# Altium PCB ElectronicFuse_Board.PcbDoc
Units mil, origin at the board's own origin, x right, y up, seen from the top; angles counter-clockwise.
Board outline 3505.03 x 1865.03 mil, 2 copper layers (Top Layer, Bottom Layer), stack 58.4 mil thick; 30 components, 15 nets, 72 pads, 10 vias.
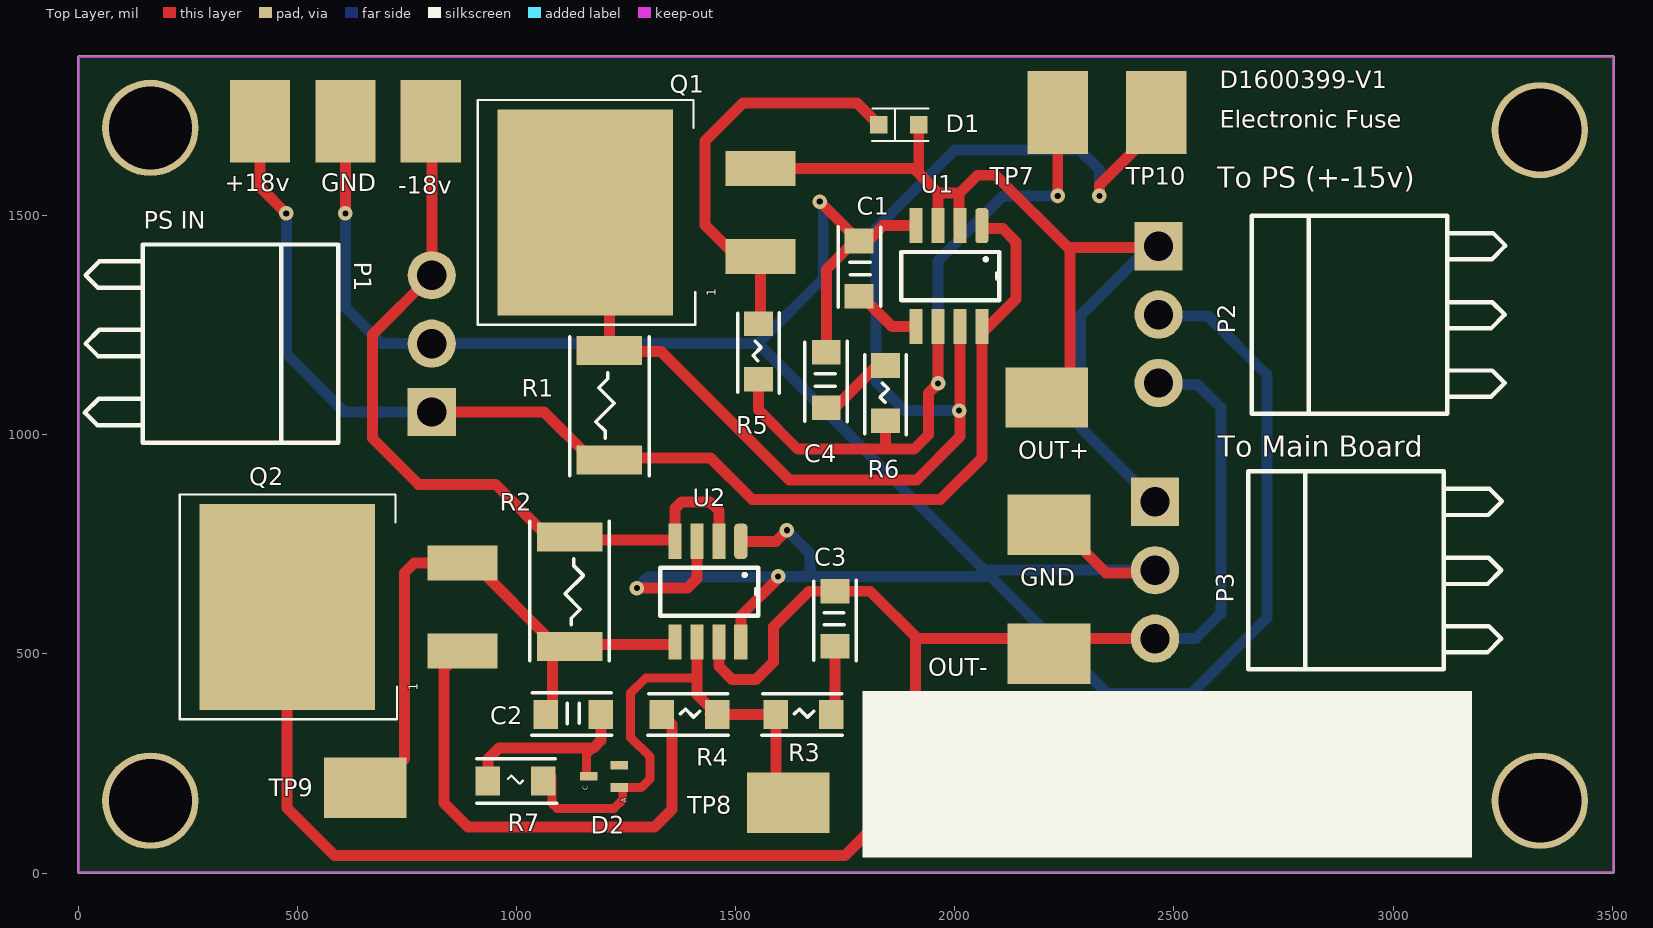
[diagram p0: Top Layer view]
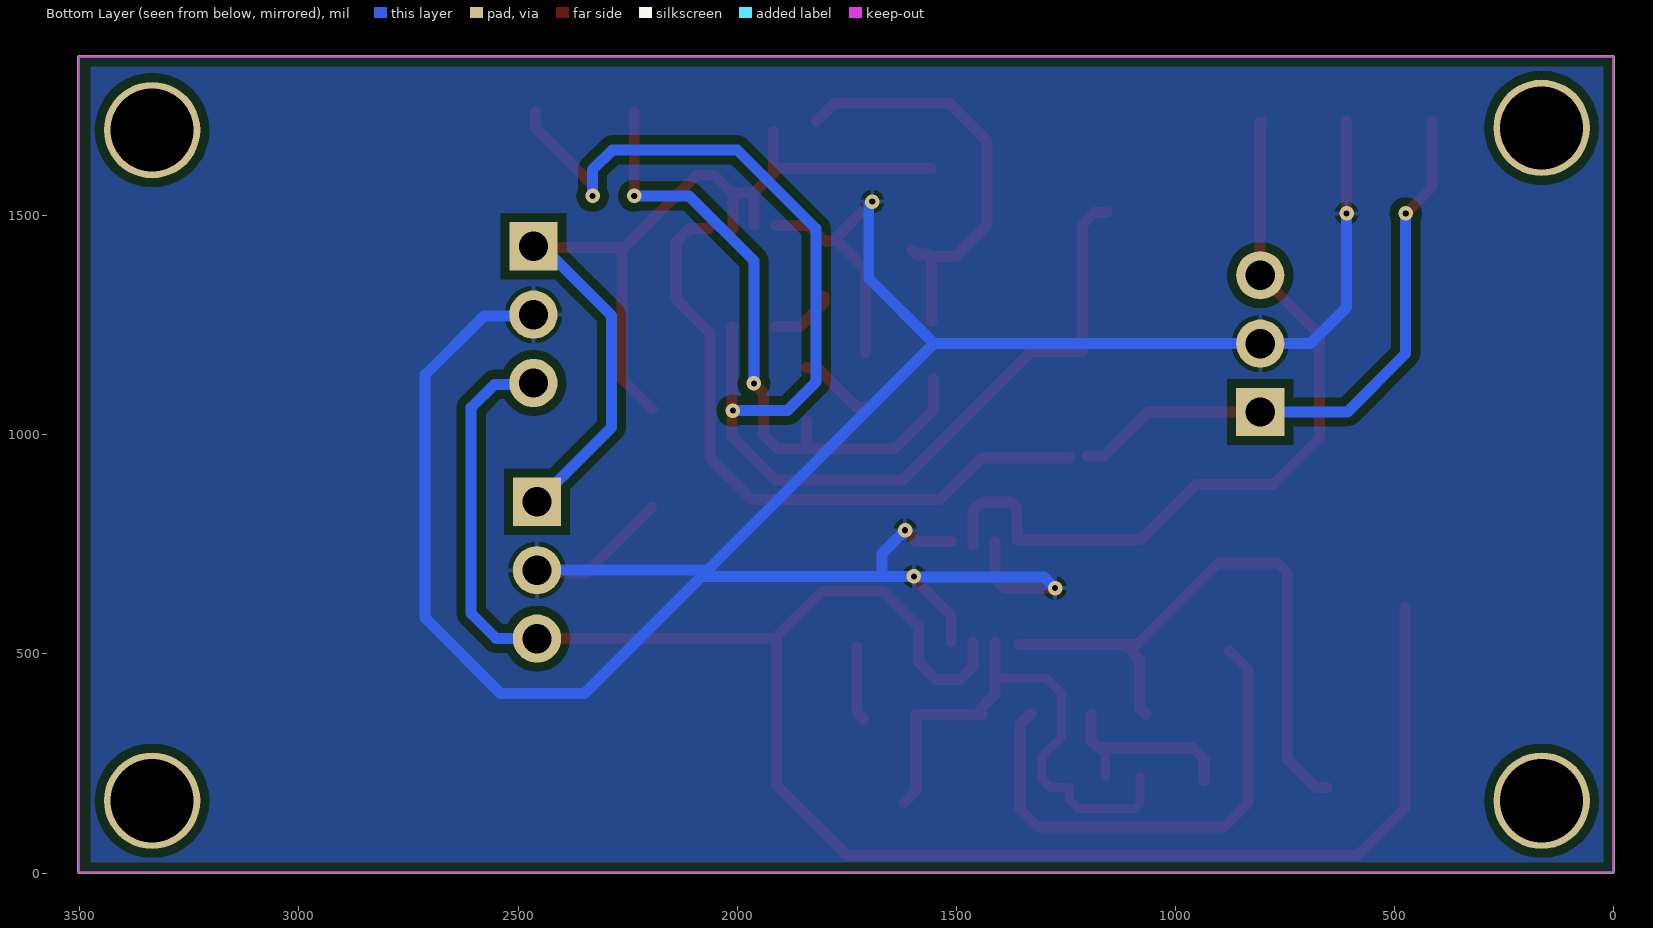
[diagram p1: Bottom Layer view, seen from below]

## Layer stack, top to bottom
Top Solder: solder mask 2.4, Solder Resist, Dk 3.5
Top Layer: signal copper 9.4
Dielectric 1: dielectric 39.6, FR-4, Dk 4.8
Bottom Layer: signal copper 9.4
Bottom Solder: solder mask 2.4, Solder Resist, Dk 3.5

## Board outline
-0.59,1.93 -0.59,1861.93 cw(c1.93,1861.93) 1.93,1864.44 3501.93,1864.44 cw(c3501.93,1861.93) 3504.44,1861.93 3504.44,1.93 cw(c3501.93,1.93) 3501.93,-0.59 1.93,-0.59 cw(c1.93,1.93)

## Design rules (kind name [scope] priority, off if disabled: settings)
Clearance [All] p1: gap=20
HoleSize [All] p1: absolutevalues=TRUE maxlimit=220 minlimit=1 maxpercent=80.000 minpercent=20.000
PolygonConnect [All] p1: connectstyle=Relief reliefconductorwidth=10 reliefentries=4 polygonreliefangle="90 Angle" airgapwidth=10
RoomDefinition ElectronicFusev2 [InComponentClass('ElectronicFusev2')] p1: confinementstyle=ConfineOut formatcopy=TRUE lockcomponents=FALSE outline 3291.93,360 3320,360 3320,413.07 3291.93,413.07
RoutingVias [All] p1: holewidth=28 width=50 viastyle="Through Hole" minholewidth=28 minwidth=50 maxholewidth=220 maxwidth=240
SilkToSilkClearance [All] p1: silktosilkclearance=5
SilkToSolderMaskClearance [IsPad] p1: minsilkscreentomaskgap=6 clearancetoexposedcopper=TRUE
SolderMaskExpansion [All] p1: expansion=4
Width [All] p1: maxlimit=25 minlimit=10 preferedwidth=10
27 further rules are at their usual default settings.

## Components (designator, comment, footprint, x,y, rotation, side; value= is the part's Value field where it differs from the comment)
+18v "TESTPT" smt_tp 415,1715 r270 top (schematic designator TP1)
-18v "TESTPT" smt_tp 805,1715 r90 top (schematic designator TP2)
C1 "SMD Capacitor 33nF 50v 1206" 1206_Cap 1781.93,1441.93 r270 top
C2 "SMD Capacitor 150nF 50v 1206" 1206_Cap 1066.93,361.93 r0 top
C3 "SMD Capacitor 3.3nF 50v X7R 1206" 1206_Cap 1726.93,516.93 r90 top
C4 "SMD Capacitor 3.3nF 50v X7R 1206" 1206_Cap 1706.93,1061.93 r90 top
D1 "MM3Z11VT1GOSCT-ND" SOD-323 1826.93,1706.93 r0 top
D2 "DIODE SCHOTTKY 40V 200MA SOT323" SOT323_Single_Diode 1235,195 r90 top
GND "TESTPT" smt_tp 2215,795 r0 top (schematic designator TP5)
GND "TESTPT" smt_tp 610,1715 r90 top (schematic designator TP3)
OUT+ "TESTPT" smt_tp 2210,1085 r180 top (schematic designator TP4)
OUT- "TESTPT" smt_tp 2215,500 r0 top (schematic designator TP6)
P1 "Molex 3p 0.156inch RA" MOLEX_156_3P_RA_PS_IN 806.93,1051.93 r180 top
P2 "Molex 3p 0.156inch RA" MOLEX_156_RA_3_PS 2465,1430 r0 top
P3 "Molex 3p 0.156inch Through Hole RA" MOLEX_156_RA_3 2456.93,846.93 r0 top
Q1 "IRF530NS" D2PAK 1556.93,1406.93 r90 top
Q2 "IRF530NS" D2PAK 876.93,506.93 r90 top
R1 "SMD Res 2512 0.06ohm 1W 1%" 2512 1211.93,941.93 r90 top
R2 "SMD Res 2512 0.06ohm 1W 1%" 2512 1121.93,766.93 r270 top
R3 "SMD Res 1206 1K 0.25W" 1206 1591.93,361.93 r0 top
R4 "SMD Res 1206 10ohm 0.25W" 1206 1331.93,361.93 r0 top
R5 "SMD Res 1206 10ohm 0.25W" 1206 1551.93,1126.93 r90 top
R6 "SMD Res 1206 100ohm 0.25W" 1206 1841.93,1031.93 r90 top
R7 "RES SMD 220 OHM 0.1% 0.4W 1206" 1206 935,210 r0 top
TP7 "TESTPT" smt_tp 2235,1735 r90 top
TP8 "TESTPT" smt_tp 1620,160 r0 top
TP9 "TESTPT" smt_tp 655,195 r0 top
TP10 "TESTPT" smt_tp 2460,1735 r90 top
U1 "LT4256-1 Positive High Voltage Hot SwapControllers" SOIC_8P_ 2061.93,1476.93 r270 top
U2 "LT4250L Neg Voltage Hot SwapController" SOIC_8P_ 1511.93,756.93 r270 top

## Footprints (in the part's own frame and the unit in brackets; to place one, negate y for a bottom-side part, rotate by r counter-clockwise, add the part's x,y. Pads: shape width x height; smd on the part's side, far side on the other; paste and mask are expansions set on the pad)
1206 [mil]
  rect 56x66 smd: 1(0,0) 2(126,0)
  silkscreen extent -32,-48 151,47, body extent -15,-40 143,40, height 21
1206_Cap [mil]
  rect 56x66 smd: 1(0,0) 2(126,0)
  silkscreen extent -32,-48 151,49, body extent -6,-40 135,40, height 10
2512 [mil]
  rect 66x150 smd: 1(0,0) 2(250,0)
  silkscreen extent -36,-91 282,90, body extent -1,-80 251,80, height 21
D2PAK [mil] "MOSFET D2PAK"
  rect 80x160 smd: 1(0,0) 3(200,0)
  rect 470x400 smd: 2(100,400)
  silkscreen extent -156,149 357,645, body extent -101,-36 304,637, height 152
MOLEX_156_3P_RA_PS_IN [mil]
  rect 110x110 hole 67: 1(0,0)
  round 110 hole 67: 2(0,-156) 3(0,-312)
  silkscreen extent 213,-382 792,70
MOLEX_156_RA_3 [mil] "3 Pin Molex, 0.156mil Spacing, Right Angle"
  rect 110x110 hole 67: 1(0,0)
  round 110 hole 67: 2(0,-156) 3(0,-312)
  silkscreen extent 213,-382 792,70
MOLEX_156_RA_3_PS [mil]
  rect 110x110 hole 67: 1(0,0)
  round 110 hole 67: 2(0,-156) 3(0,-312)
  silkscreen extent 213,-382 792,70
smt_tp [mm] "Surface Mount Test Point"
  rect 4.8x3.5 smd: 1(0,0)
SOD-323 [mil] "SOD-323 diode"
  rect 40x40 smd: 1(0,0) 2(91,0)
  silkscreen extent -15,-37 113,37, body extent -10,-27 100,27, height 42
SOIC_8P_ [mil]
  rrect50% 80x30 smd: 1(0,0)
  rect 80x30 smd: 2(0,-50) 3(0,-100) 4(0,-150) 5(230,-150) 6(230,-100) 7(230,-50) 8(230,0)
  silkscreen extent 60,-184 170,40, body extent -33,-180 264,35, height 72
SOT323_Single_Diode [mil]
  rect 20x40 smd: 1(0,0) 2(51,0) 3(26,70)
  body extent -25,-16 75,87, height 40

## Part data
+18v -18v GND GND OUT+ OUT- TP7 TP8 TP9 TP10: "PCB Testpoint"
C1: library part CAP_1206_33nF
C2: library part CAP_1206_150nF
C3 C4: library part CAP_1206_3.3nF, "SMD Capacitor 3.3nF 50v 1206"
D1: "Zener Diode 11v 300mW SOD-323"
D2: library part BAT854W_SOT323
P1: library part "Header 3p 156 IN"
P2: library part "Header 3p 156 Out PS"
P3: library part "Header 3p 156 out", "Molex 3p 0.156inch RA"
Q1 Q2: "MOSFET N-CH 100V 17A D2PAK"
R1 R2: library part 2512_0.06
R3: library part 1206_Res_1K
R4 R5: library part 1206_10
R6: library part 1206_100
R7: library part 1206_Res_220
U1: library part LT4256-1, "Hot Swap Controllers 10.8v to 80v"
U2: library part LT4250L, "Negative Volage Hot Swap Controller"

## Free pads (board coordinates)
  round 220 hole 190: 1(165,1700) 2(3335,1695) 3(3335,165) 4(165,165)

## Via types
v1: diameter 33, hole 14, Top Layer to Bottom Layer, 10 vias

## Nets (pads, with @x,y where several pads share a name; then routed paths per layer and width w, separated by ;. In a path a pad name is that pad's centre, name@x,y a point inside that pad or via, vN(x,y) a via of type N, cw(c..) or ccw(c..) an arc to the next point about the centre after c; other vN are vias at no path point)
GND: C1.1 C4.2 GND.1 P1.2 P2.2 P3.2 U1.4 U2.1 U2.3 U2.8 | length 6943.3
  Top Layer w25: v1(610,1505) GND.1@610,1715 ; v1(1275,650) 1390,650 1411.93,671.93 U2.3 ; U2.8 1511.93,586.93 v1@1600,675 ; U2.1 1591.93,756.93 v1(1616.93,781.93) ; v1(1691.93,1531.93) C1.1 ; C4.2 1706.93,1376.93 1771.93,1441.93 C1.1 ; U1.4 1836.93,1476.93 1801.93,1441.93 C1.1 ; GND.1@2195,835 2345,685 P3.2@2451,685
  Bottom Layer w25: v1(610,1505) 610,1290 692.07,1207.93 P1.2 1550.92,1207.93 ; v1(1275,650) 1300,675 1595,675 v1(1596.93,676.93) 1670,676.93 ; v1(1616.93,781.93) 1670,728.85 1670,676.93 ; v1(1691.93,1531.93) 1700,1523.85 1700,1357 1550.92,1207.93 ; P3.2 2067.92,690.93 1550.92,1207.93 ; P2.2@2456.93,1270.93 2577.93,1270.93 2711.93,1136.93 2711.93,581.93 2540,410 2348.85,410 2081.93,676.93 1670,676.93
NetC1_2: C1.2 U1.5 | length 146.8
  Top Layer w25: C1.2@1801.93,1315.93 1801.93,1301.93 1856.93,1246.93 U1.5
NetC2_1: C2.1 Q2.3 R2.2 TP9.1 U2.5 | length 1420.3
  Top Layer w25: TP9.1 680,195 745,260 745,685 766.93,706.93 Q2.3 901.92,706.93 1086.93,521.93 U2.5@1356.93,521.93 ; C2.1 1081.93,376.93 1081.93,486.93 R2.2@1116.93,521.93
NetC2_2: C2.2 D2.3 R7.1 | length 455.6
  Top Layer w20: D2.3@1160,221 1160,270 1175.5,285.5
  Top Layer w25: R7.1 935,260 960.5,285.5 1175.5,285.5 1192.93,302.93 C2.2
NetC3_1: C3.1 R3.2 | length 171.2
  Top Layer w25: R3.2@1711.93,351.93 1726.93,366.93 C3.1
NetC3_2: C3.2 OUT-.1 P2.3 P3.3 Q2.2 U2.7 | length 4541.4
  Top Layer w25: Q2.2 476.93,148.07 585,40 1750,40 1910,200 1910,539.85 1806.93,642.93 ; U2.7 1461.93,471.93 1491.93,441.93 1546.93,441.93 1586.93,481.93 1586.93,561.93 1667.93,642.93 1806.93,642.93 ; P3.3 1914.93,534.93 1806.93,642.93
  Bottom Layer w25: P3.3 2549.93,534.93 2606.93,591.93 2606.93,1061.93 2553.92,1114.93 P2.3@2456.93,1114.93
NetC4_1: C4.1 R6.2 | length 172.7
  Top Layer w25: C4.1 1726.93,1061.93 1817.93,1152.93 R6.2@1841.93,1152.93
NetD1_1: D1.1 Q1.1 R5.2 | length 986.1
  Top Layer w25: R5.2@1556.93,1257.93 Q1.1 1501.92,1406.93 1430,1478.85 1430,1670 1516.93,1756.93 1776.93,1756.93 D1.1@1819.43,1714.43 ; Q1.1@1566.93,1411.93 Q1.1@1591.93,1411.93 ; Q1.1@1586.93,1406.93 Q1.1@1591.93,1411.93 ; Q1.1@1601.93,1421.93 Q1.1@1591.93,1411.93
NetD1_2: D1.2 OUT+.1 P2.1 P3.1 Q1.3 U1.2 U1.3 | length 2437.7
  Top Layer w25: Q1.3 1906.92,1606.93 1961.93,1551.93 ; 1917.93,1596.93 D1.2@1917.93,1691.93 ; U1.3 1961.93,1551.93 ; U1.2@2010,1470 2010,1551.93 ; OUT+.1@2195,1060 2262.5,1127.5 2262.5,1422.5 2093.07,1591.93 2051.93,1591.93 2011.93,1551.93 1961.93,1551.93 ; 2258.07,1426.93 P2.1@2461.93,1426.93 ; P3.1@2423.85,880 P3.1
  Bottom Layer w25: P3.1 2286.93,1016.93 2286.93,1271.93 2441.93,1426.93 P2.1@2456.93,1426.93
NetD2_1: D2.1 R3.1 R4.2 R7.2 TP8.1 U2.6 | length 1316.7
  Top Layer w20: R7.2@1081,220 1081,159 1092.5,147.5 1222.5,147.5 1242.5,167.5 1242.5,195 1285,195 1305,215 1305,265 1260,310 1260,410 1295,445 1410,445
  Top Layer w25: 1411.93,443.07 U2.6 ; U2.6@1411.93,506.93 1411.93,406.93 R4.2@1452.43,366.43 ; R4.2@1441.93,361.93 R4.2 R3.1 1591.93,188.07 TP8.1
NetP1_1: +18v.1 P1.1 R1.1 U1.1 U1.8 | length 2889.9
  Top Layer w25: +18v.1 415,1565 v1(475,1505) ; P1.1 1063.07,1051.93 1163.07,951.93 R1.1@1201.93,951.93 ; R1.1@1241.93,946.93 1443.07,946.93 1538.07,851.93 1966.93,851.93 2061.93,946.93 2061.93,1231.93 2140,1310 2140,1440 2110,1470 U1.1@2065,1470
  Bottom Layer w25: v1(475,1505) 475,1185 608.07,1051.93 P1.1
NetP1_3: -18v.1 P1.3 R2.1 U2.2 U2.4 | length 1832.3
  Top Layer w25: -18v.1 806.93,1713.07 P1.3 671.93,1228.93 671.93,991.93 776.93,886.93 951.93,886.93 1078.85,760 1361.93,760 1361.93,831.93 1376.93,846.93 1441.93,846.93 1461.93,826.93 U2.2@1461.93,746.93
NetQ1_2: Q1.2 R1.2 TP10.1 U1.7 | length 3047.6
  Top Layer w25: Q1.2 1185,1506.93 1211.93,1480 R1.2 1213.85,1190 1330,1190 1623.07,896.93 1913.29,896.93 2011.93,995.56 U1.7 ; v1@2330,1540 v1(2330,1545) 2330,1570 2460,1700 TP10.1
  Bottom Layer w25: v1(2010,1055) 1885,1055 1820,1120 1820,1470 2000,1650 2285,1650 2330,1605 v1(2330,1545)
NetQ2_1: Q2.1 R4.1 | length 1153.7
  Top Layer w25: Q2.1 835,465 835,160 890,105 1315,105 1355,145 1355,338.85 R4.1@1329.43,364.43
NetR5_1: R5.1 R6.1 TP7.1 U1.6 | length 1641.5
  Top Layer w25: R5.1 1551.93,1056.93 1641.93,966.93 1836.93,966.93 ; R6.1 1841.93,971.93 1836.93,966.93 ; U1.6 v1(1961.93,1116.93) 1940,1095 1940,1000 1906.93,966.93 1836.93,966.93 ; v1@2235,1540 v1(2235,1545) TP7.1
  Bottom Layer w25: v1(1961.93,1116.93) 1961.93,1396.93 2110,1545 v1(2235,1545)
pads on no net: D2.2

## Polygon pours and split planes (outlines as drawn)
GND on Bottom Layer "BottomPadLayer" (solid, remove dead copper, pour order 9): 20,1850 20,30 25,25 3475,25 3475,1850 3480,1855

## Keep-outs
Keep-Out Layer:
  lines w5: 1.93,1.93 1.93,1861.93 3501.93,1861.93 3501.93,1.93 1.93,1.93

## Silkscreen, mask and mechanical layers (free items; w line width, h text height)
Top Overlay:
  region: 3180,415 1790,415 1790,35 3180,35
  text "D1600399-V1" at 2605,1790 h40
  text "Electronic Fuse" at 2605,1700 h40
Mechanical 1:
  lines w5: 1.93,1.93 1.93,1861.93 3501.93,1861.93 3501.93,1.93 1.93,1.93
  lines w10: -93.07,61.93 -73.07,1.93 ; -93.07,1801.93 -73.07,1861.93 ; -83.07,1.93 -63.07,1.93 ; -83.07,1861.93 -63.07,1861.93 ; -73.07,656.01 -73.07,1.93 ; -73.07,1207.84 -73.07,1861.93 ; -53.07,61.93 -73.07,1.93 ; -53.07,1801.93 -73.07,1861.93 ; 2.84,-70.14 2.87,-50.14 ; 62.82,-80.22 2.85,-60.14 ; 62.88,-40.22 2.85,-60.14 ; 1356.98,-62.07 2.85,-60.14 ; 2148.73,-63.2 3502.85,-65.14 ; 3442.82,-85.05 3502.85,-65.14 ; 3442.88,-45.05 3502.85,-65.14 ; 3502.84,-75.14 3502.87,-55.14
  text "1860 (mil)" at -37.08,666.01 h40 r90
  text "3500.004 (mil)" at 1366.93,-98.07 h40 r359.92
Drill Drawing:
  circle w10: c53.44,2298.38 r21.3
  lines w10: 32.15,2096.05 42.79,2096.05 53.44,2085.41 64.09,2096.05 74.74,2096.05 64.09,2106.7 74.74,2117.35 64.09,2117.35 53.44,2128 42.79,2117.35 32.15,2117.35 42.79,2106.7 32.15,2096.05 ; 32.15,2181.24 74.74,2181.24 74.74,2223.84 32.15,2223.84 32.15,2181.24
  lines w15: -7.18,2056.65 2528.9,2056.65 ; -7.18,2344.16 2528.9,2344.16 ; 356.33,1960.82 356.33,2440 ; 813.73,1960.82 813.73,2440 ; 1685,1960.82 1685,2440 ; 2019.76,1960.82 2019.76,2440 ; -7.18,1960.82 2528.9,1960.82 2528.9,2440 -7.18,2440 -7.18,1960.82
  text "Symbol" at 50.32,2372.91 h46
  text "Hit Count" at 385.08,2372.91 h46
  text "Finished Hole Size" at 842.48,2372.91 h46
  text "Plated" at 1713.75,2372.91 h46
  text "Hole Type" at 2048.51,2372.91 h46
  text "4" at 385.08,2277.08 h38.33
  text "190.00mil (4.826mm)" at 842.48,2277.08 h38.33
  text "PTH" at 1713.75,2277.08 h38.33
  text "Round" at 2048.51,2277.08 h38.33
  text "9" at 385.08,2181.24 h38.33
  text "67.00mil (1.702mm)" at 842.48,2181.24 h38.33
  text "PTH" at 1713.75,2181.24 h38.33
  text "Round" at 2048.51,2181.24 h38.33
  text "10" at 385.08,2085.41 h38.33
  text "14.00mil (0.356mm)" at 842.48,2085.41 h38.33
  text "PTH" at 1713.75,2085.41 h38.33
  text "Round" at 2048.51,2085.41 h38.33
  text "23 Total" at 385.08,1989.57 h38.33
